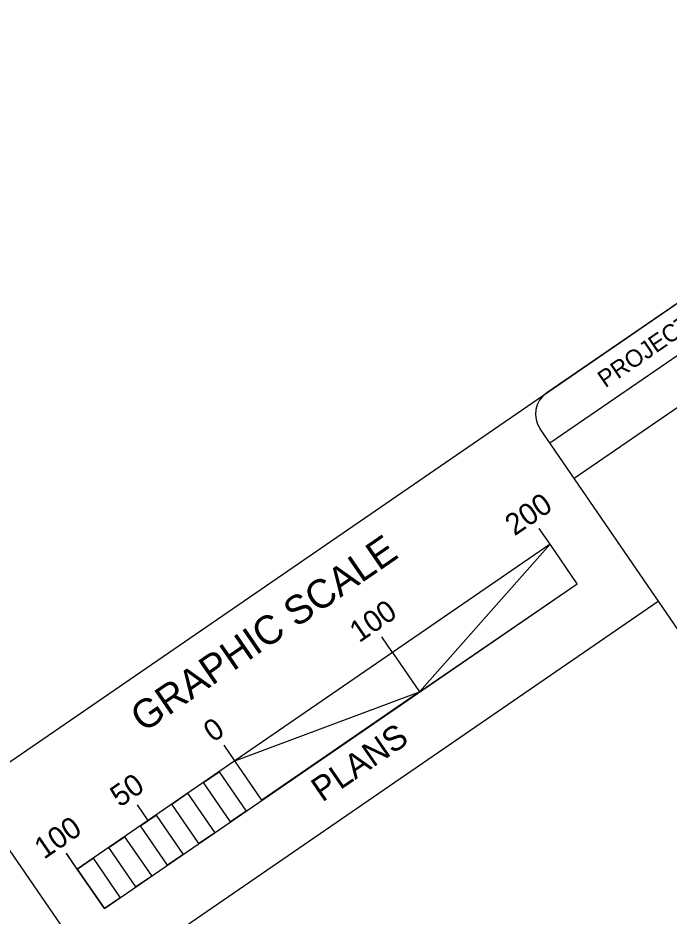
# Model space of a CAD drawing. Extents: x 2385901 to 2398444, y 552503 to 560579.
# Drawn here: x 2396692.6 to 2397033.1, y 560053.3 to 560522.9 of the extents above; entities that cross this region are included whole.
import ezdxf

# ---------------------------------------------------------------- set-up
doc = ezdxf.new("R2010")
doc.units = 0
for name, color, linetype in [('Exist Property Deed Book Text', 7, 'Continuous'), ('Old_Level_12', 7, 'Continuous'), ('Old_Level_8', 7, 'Continuous'), ('Prop EOT', 7, 'Continuous'), ('SITE_2_BUFFER_RESTORATION', 7, 'Continuous')]:
    doc.layers.add(name, color=color, linetype=linetype)

msp = doc.modelspace()

# ---------------------------------------------------------------- linework, layer by layer
at = {"layer": 'Old_Level_12'}
msp.add_line((2396781.34, 560117.46), (2396795.49, 560096.85), dxfattribs=at)
for points in [[(2396970.92, 560247.68), (2396902.65, 560170.46), (2396985.09, 560227.06)], [(2396806.08, 560134.43), (2396902.65, 560170.46), (2396820.23, 560113.82)], [(2396789.58, 560123.12), (2396797.82, 560128.78), (2396811.99, 560108.16), (2396803.73, 560102.52)], [(2396773.11, 560111.78), (2396781.34, 560117.46), (2396795.49, 560096.85), (2396787.25, 560091.19)], [(2396756.62, 560100.45), (2396764.86, 560106.12), (2396779, 560085.53), (2396770.76, 560079.87)], [(2396740.12, 560089.15), (2396748.38, 560094.79), (2396762.53, 560074.19), (2396754.31, 560068.54)], [(2396723.64, 560077.83), (2396731.88, 560083.49), (2396746.03, 560062.88), (2396737.79, 560057.22)]]:
    msp.add_lwpolyline(points, close=True, dxfattribs=at)
at = {"layer": 'Old_Level_8'}
for p, q in [((2397254.96, 560522.91), (2396969.16, 560326.85)), ((2396970.74, 560300.68), (2397267.67, 560504.37)), ((2397280.4, 560485.82), (2396983.46, 560282.12)), ((2397154.02, 560033.5), (2396965.64, 560308.1)), ((2396736.07, 560017.83), (2397027.46, 560217.98)), ((2396666.54, 560119.05), (2396736.07, 560017.83))]:
    msp.add_line(p, q, dxfattribs=at)
msp.add_arc((2396976.79, 560315.72), 13.5, 124.45, 214.45, dxfattribs=at)
at = {"layer": 'Prop EOT'}
msp.add_lwpolyline([(2397254.96, 560522.91), (2394782.07, 558824.3), (2395971.07, 557093.32), (2398443.91, 558791.91)], close=True, dxfattribs=at)
at = {"layer": 'SITE_2_BUFFER_RESTORATION'}
for p, q in [((2396970.94, 560247.7), (2396965.26, 560255.96)), ((2396970.92, 560247.68), (2396965.26, 560255.93)), ((2396970.92, 560247.68), (2396723.64, 560077.83)), ((2396985.09, 560227.06), (2396970.92, 560247.68)), ((2396737.79, 560057.22), (2396985.09, 560227.06)), ((2396888.49, 560191.07), (2396882.84, 560199.29)), ((2396888.5, 560191.1), (2396882.85, 560199.32)), ((2396888.49, 560191.07), (2396902.65, 560170.46)), ((2396806.08, 560134.43), (2396800.42, 560142.67)), ((2396760.74, 560103.25), (2396755.09, 560111.47)), ((2396760.74, 560103.29), (2396755.1, 560111.51)), ((2396760.74, 560103.25), (2396760.74, 560103.25)), ((2396723.64, 560077.83), (2396717.99, 560086.05)), ((2396723.64, 560077.86), (2396718, 560086.09)), ((2396723.64, 560077.83), (2396737.79, 560057.22)), ((2396723.64, 560077.83), (2396723.64, 560077.83))]:
    msp.add_line(p, q, dxfattribs=at)

# ---------------------------------------------------------------- texts
at = {"layer": 'Exist Property Deed Book Text'}
msp.add_text('PROJECT REFERENCE NO.', height=9.0002, rotation=34.45, dxfattribs=at).set_placement((2396999.79, 560329.23))
at = {"layer": 'Old_Level_12'}
for s, p in [('200', (2396952.34, 560251.79)), ('100', (2396871.04, 560195.91)), ('0', (2396794.65, 560143.77)), ('50', (2396745.84, 560109.85)), ('100', (2396706.19, 560082.67))]:
    msp.add_text(s, height=11.25, rotation=34.4849, dxfattribs=at).set_placement(p)
at = {"layer": 'Old_Level_8'}
msp.add_text('GRAPHIC SCALE', height=14.9998, rotation=34.4849, dxfattribs=at).set_placement((2396758.24, 560148.95))
at = {"layer": 'SITE_2_BUFFER_RESTORATION'}
msp.add_text('PLANS', height=12.749, rotation=34.4849, dxfattribs=at).set_placement((2396851.75, 560112.57))

doc.saveas('drawing.dxf')
